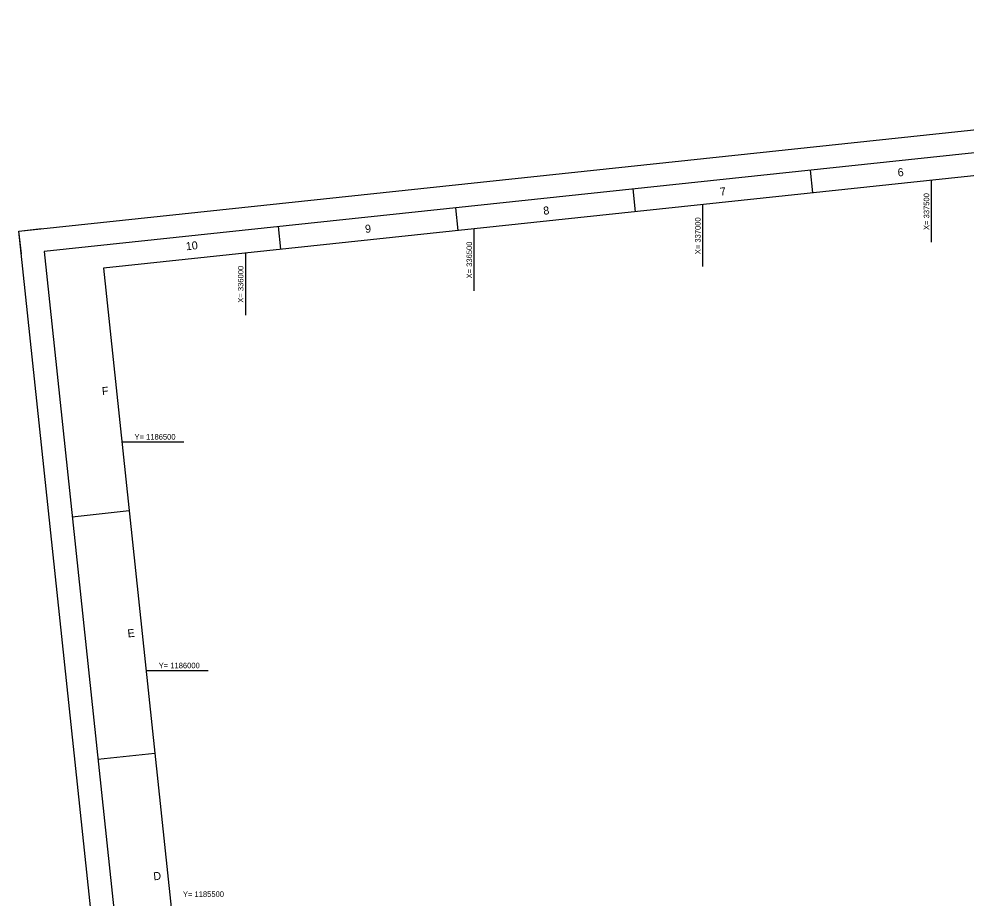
# Model space of a CAD drawing. Extents: x 335504 to 340238, y 1183580 to 1187425.
# Drawn here: x 335504 to 337576, y 1185502 to 1187425 of the extents above; entities that cross this region are included whole.
import ezdxf

# ---------------------------------------------------------------- set-up
doc = ezdxf.new("R2010")
doc.units = 0
for name, color, linetype in [('G-ANNO-NPLT', 7, 'Continuous'), ('G-ANNO-TTLB', 7, 'Continuous'), ('V-TOPO-COOR-STAT', 7, 'Continuous')]:
    doc.layers.add(name, color=color, linetype=linetype)

msp = doc.modelspace()

# ---------------------------------------------------------------- linework, layer by layer
at = {"layer": 'G-ANNO-NPLT'}
msp.add_lwpolyline([(335504, 1186961.1), (339879.5, 1187424.9), (340237.8, 1184043.9), (335862.4, 1183580.1)], close=True, dxfattribs=at)
msp.add_lwpolyline([(335509.3, 1186911.4), (335504, 1186961.1), (335553.7, 1186966.4)], dxfattribs=at)
at = {"layer": 'G-ANNO-TTLB'}
for p, q in [((337234.6, 1187094.3), (337239.9, 1187044.6)), ((336846.8, 1187053.2), (336852, 1187003.4)), ((336458.9, 1187012.1), (336464.2, 1186962.3)), ((336458.9, 1187012.1), (336464.2, 1186962.3)), ((336071.1, 1186971), (336076.4, 1186921.2)), ((335620.5, 1186336.4), (335744.8, 1186349.6)), ((335676.7, 1185806.1), (335801, 1185819.3))]:
    msp.add_line(p, q, dxfattribs=at)
for points in [[(335906.8, 1183635.1), (340182.8, 1184088.3), (339835, 1187369.9), (335559, 1186916.7)], [(339790.6, 1187314.9), (335688.6, 1186880.1), (336025.9, 1183698), (340127.9, 1184132.8)]]:
    msp.add_lwpolyline(points, close=True, dxfattribs=at)
at = {"layer": 'V-TOPO-COOR-STAT'}
for p, q in [((337500, 1186936.4), (337500, 1187072.1)), ((337000, 1186883.4), (337000, 1187019.1)), ((336500, 1186830.4), (336500, 1186966.1)), ((336000, 1186777.4), (336000, 1186913.1)), ((335728.9, 1186500), (335864.6, 1186500)), ((335781.9, 1186000), (335917.6, 1186000))]:
    msp.add_line(p, q, dxfattribs=at)

# ---------------------------------------------------------------- texts
at = {"layer": 'G-ANNO-TTLB'}
for s, p in [('6', (337426.9, 1187080.2)), ('7', (337038.2, 1187038.3)), ('8', (336651.8, 1186996.6)), ('9', (336262, 1186956.9)), ('10', (335870, 1186918.9)), ('F', (335686.4, 1186602)), ('E', (335742.4, 1186072.2)), ('D', (335798.9, 1185541.1))]:
    msp.add_text(s, height=17.5, rotation=6.0506, dxfattribs=at).set_placement(p)
at = {"layer": 'V-TOPO-COOR-STAT'}
for s, p in [('X= 337500', (337495, 1186963.4)), ('X= 337000', (336995, 1186910.4)), ('X= 336500', (336495, 1186857.4)), ('X= 336000', (335995, 1186804.4))]:
    msp.add_text(s, height=12, rotation=90, dxfattribs=at).set_placement(p)
for s, p in [('Y= 1186500', (335756.7, 1186505)), ('Y= 1186000', (335809.7, 1186005)), ('Y= 1185500', (335862.7, 1185505))]:
    msp.add_text(s, height=12, dxfattribs=at).set_placement(p)

doc.saveas('drawing.dxf')
